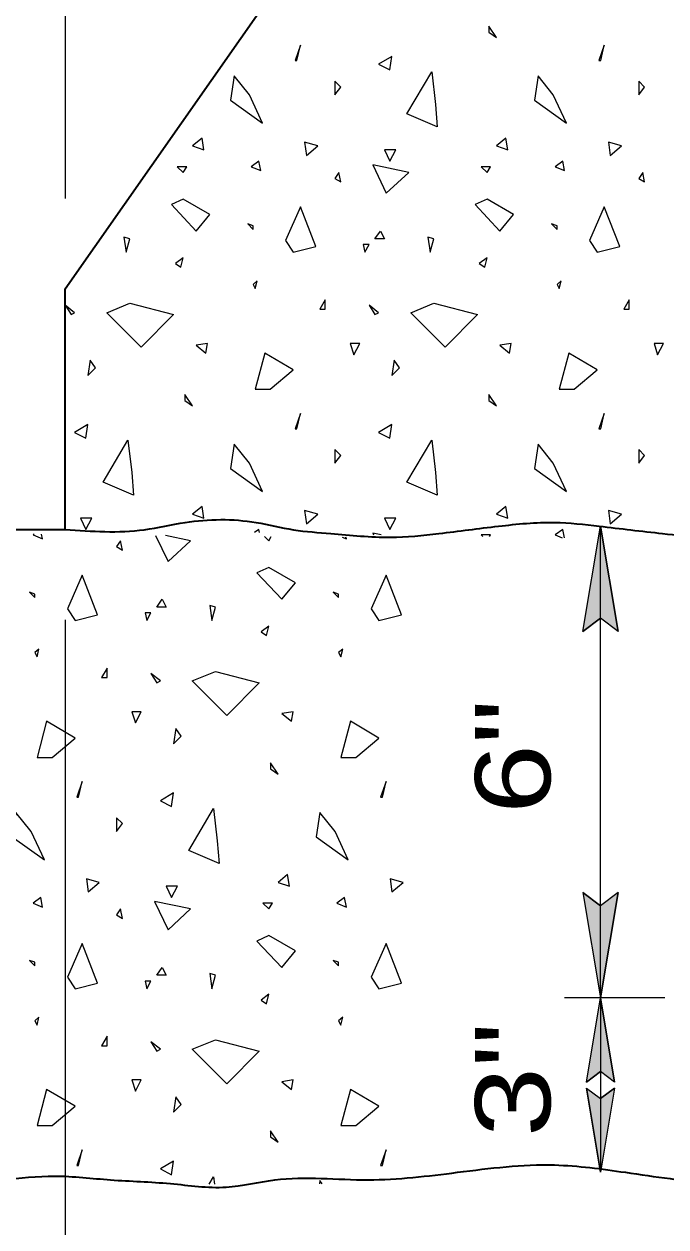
# Model space of a CAD drawing. Extents: x -9.07 to -2.08, y 8.04 to 17.77.
# Drawn here: x -6.844 to -6.332, y 13.739 to 14.699 of the extents above; entities that cross this region are included whole.
import ezdxf
from ezdxf.enums import TextEntityAlignment as Align

# ---------------------------------------------------------------- set-up
doc = ezdxf.new("R2010")
doc.units = 0
doc.header["$LTSCALE"] = 0.024
for name, color, linetype, lineweight in [('1', 7, 'Continuous', 35), ('10', 7, 'Continuous', 13), ('12', 7, 'Continuous', 53), ('6', 7, 'Continuous', 13)]:
    doc.layers.add(name, color=color, linetype=linetype, lineweight=lineweight)

msp = doc.modelspace()

# ---------------------------------------------------------------- hatches: boundary and pattern name
at = {"layer": '10'}
for points in [[(-6.38383, 14.29833), (-6.36983, 14.21433), (-6.38383, 14.22483), (-6.39783, 14.21433)], [(-6.38383, 13.922), (-6.36983, 14.00617), (-6.38383, 13.9955), (-6.39783, 14.00617)], [(-6.38383, 13.922), (-6.37267, 13.85483), (-6.38383, 13.86333), (-6.395, 13.85483)], [(-6.38383, 13.84167), (-6.37267, 13.85), (-6.38383, 13.78283), (-6.395, 13.85)]]:
    msp.add_hatch(color=256, dxfattribs=at).paths.add_polyline_path(points)

# ---------------------------------------------------------------- linework, layer by layer
at = {"layer": '1'}
msp.add_lwpolyline([(-7.227, 13.773), (-7.227, 14.29567), (-6.81067, 14.29567), (-6.81067, 14.48783), (-6.4615, 14.98667)], dxfattribs=at)
at = {"layer": '10'}
for p, q in [((-6.81067, 17.69383), (-6.81067, 14.55983)), ((-6.39783, 14.21433), (-6.38383, 14.29833)), ((-6.38383, 13.922), (-6.38383, 14.29833)), ((-6.36983, 14.21433), (-6.38383, 14.29833)), ((-6.81067, 14.22367), (-6.81067, 13.45733)), ((-6.39783, 14.21433), (-6.38383, 14.22483)), ((-6.36983, 14.21433), (-6.38383, 14.22483)), ((-6.39783, 14.00617), (-6.38383, 13.922)), ((-6.39783, 14.00617), (-6.38383, 13.9955)), ((-6.36983, 14.00617), (-6.38383, 13.922)), ((-6.36983, 14.00617), (-6.38383, 13.9955)), ((-6.33267, 13.922), (-6.41267, 13.922)), ((-6.395, 13.85483), (-6.38383, 13.922)), ((-6.38383, 13.922), (-6.38383, 13.78283)), ((-6.37267, 13.85483), (-6.38383, 13.922)), ((-6.395, 13.85483), (-6.38383, 13.86333)), ((-6.37267, 13.85483), (-6.38383, 13.86333)), ((-6.395, 13.85), (-6.38383, 13.78283)), ((-6.395, 13.85), (-6.38383, 13.84167)), ((-6.37267, 13.85), (-6.38383, 13.78283)), ((-6.37267, 13.85), (-6.38383, 13.84167))]:
    msp.add_line(p, q, dxfattribs=at)
for points in [[(-6.38383, 14.29833), (-6.36983, 14.21433), (-6.38383, 14.22483), (-6.39783, 14.21433)], [(-6.38383, 13.922), (-6.36983, 14.00617), (-6.38383, 13.9955), (-6.39783, 14.00617)], [(-6.38383, 13.922), (-6.37267, 13.85483), (-6.38383, 13.86333), (-6.395, 13.85483)], [(-6.38383, 13.84167), (-6.37267, 13.85), (-6.38383, 13.78283), (-6.395, 13.85)]]:
    msp.add_lwpolyline(points, close=True, dxfattribs=at)
at = {"layer": '10', "lineweight": 35}
for points in [[(-6.81067, 14.29567), (-6.74767, 14.2955), (-6.715, 14.30133), (-6.6585, 14.30133), (-6.62867, 14.2955), (-6.599, 14.2925), (-6.55133, 14.2895), (-6.51267, 14.2925), (-6.46517, 14.29833), (-6.4205, 14.30133), (-6.38483, 14.29833), (-6.33433, 14.2925), (-6.27183, 14.2865), (-6.21533, 14.2895), (-6.141, 14.31917), (-6.10233, 14.31317), (-6.03383, 14.30733), (-5.9715, 14.32217), (-5.9, 14.337), (-5.86133, 14.334), (-5.81683, 14.325), (-5.77217, 14.334), (-5.7245, 14.34283), (-5.674, 14.34583), (-5.6115, 14.33983), (-5.59367, 14.33983), (-5.57283, 14.34583), (-5.54017, 14.35767), (-5.4985, 14.3725), (-5.43017, 14.3725), (-5.39733, 14.38133), (-5.3765, 14.40217), (-5.34983, 14.417), (-5.32, 14.417), (-5.28433, 14.414), (-5.26067, 14.414), (-5.22783, 14.42283), (-5.216, 14.42883), (-5.19733, 14.4195)], [(-7.227, 13.773), (-7.173, 13.768), (-7.10767, 13.77383), (-7.057, 13.77683), (-7.0095, 13.771), (-6.97083, 13.771), (-6.947, 13.771), (-6.8875, 13.77383), (-6.86067, 13.77683), (-6.819, 13.77983), (-6.7745, 13.77683), (-6.72683, 13.77383), (-6.68233, 13.771), (-6.64367, 13.77683), (-6.56917, 13.77683), (-6.49783, 13.78283), (-6.4205, 13.78867), (-6.364, 13.78283), (-6.29267, 13.77383), (-6.23017, 13.771), (-6.144, 13.768), (-6.04883, 13.771), (-5.9685, 13.77983), (-5.897, 13.78867), (-5.79, 13.78283), (-5.70967, 13.771), (-5.6085, 13.765), (-5.53717, 13.765), (-5.4895, 13.768), (-5.436, 13.77983), (-5.3855, 13.78867), (-5.323, 13.78867), (-5.2725, 13.77983), (-5.23083, 13.77383), (-5.16533, 13.765), (-5.094, 13.762), (-4.99883, 13.77683), (-4.94533, 13.78283), (-4.88883, 13.78283), (-4.84417, 13.77683), (-4.82333, 13.77383), (-4.78083, 13.75633), (-4.8115, 13.771)]]:
    msp.add_spline(points, degree=3, dxfattribs=at)
at = {"layer": '6'}
for points in [[(-6.473, 14.69717), (-6.473, 14.6925), (-6.46683, 14.68817)], [(-6.62733, 14.66983), (-6.626, 14.66983), (-6.623, 14.682)], [(-6.38517, 14.66983), (-6.38367, 14.66983), (-6.38083, 14.682)], [(-6.56083, 14.667), (-6.55183, 14.66233), (-6.55033, 14.673)], [(-6.676, 14.65767), (-6.67883, 14.63817), (-6.65333, 14.61983), (-6.66383, 14.6425)], [(-6.5155, 14.63483), (-6.514, 14.61683), (-6.53817, 14.62733), (-6.51833, 14.66083)], [(-6.43367, 14.65767), (-6.4365, 14.63817), (-6.411, 14.61983), (-6.4215, 14.6425)], [(-6.59567, 14.65333), (-6.59567, 14.6425), (-6.591, 14.64867)], [(-6.35333, 14.65333), (-6.35333, 14.6425), (-6.34867, 14.64867)], [(-6.7015, 14.60783), (-6.70917, 14.60183), (-6.70017, 14.5985)], [(-6.45933, 14.60783), (-6.46683, 14.60183), (-6.45783, 14.5985)], [(-6.61983, 14.60467), (-6.61833, 14.59417), (-6.60933, 14.60183)], [(-6.55617, 14.5985), (-6.55183, 14.5895), (-6.54717, 14.5985)], [(-6.3775, 14.60467), (-6.37617, 14.59417), (-6.367, 14.60183)], [(-6.66233, 14.58517), (-6.65483, 14.582), (-6.65617, 14.5895)], [(-6.42, 14.58517), (-6.4125, 14.582), (-6.41383, 14.5895)], [(-6.72133, 14.58517), (-6.71667, 14.5805), (-6.71383, 14.58517)], [(-6.59567, 14.57583), (-6.591, 14.573), (-6.5925, 14.5805)], [(-6.5655, 14.58667), (-6.55467, 14.564), (-6.53667, 14.5805)], [(-6.479, 14.58517), (-6.47433, 14.5805), (-6.4715, 14.58517)], [(-6.35333, 14.57583), (-6.34867, 14.573), (-6.35017, 14.5805)], [(-6.726, 14.555), (-6.70633, 14.53367), (-6.6955, 14.547), (-6.71667, 14.55933)], [(-6.48367, 14.555), (-6.464, 14.53367), (-6.45317, 14.547), (-6.47433, 14.55933)], [(-6.62883, 14.51683), (-6.61083, 14.5215), (-6.623, 14.55317), (-6.635, 14.52617)], [(-6.3865, 14.51683), (-6.3685, 14.5215), (-6.38083, 14.55317), (-6.39267, 14.52617)], [(-6.66083, 14.538), (-6.66517, 14.5395), (-6.66083, 14.53517)], [(-6.55933, 14.53367), (-6.55617, 14.52767), (-6.56367, 14.52767)], [(-6.4185, 14.538), (-6.42283, 14.5395), (-6.4185, 14.53517)], [(-6.76383, 14.529), (-6.762, 14.51683), (-6.75917, 14.52767)], [(-6.573, 14.523), (-6.57167, 14.51683), (-6.56833, 14.523)], [(-6.5215, 14.529), (-6.51967, 14.51683), (-6.51683, 14.52767)], [(-6.72283, 14.50783), (-6.7185, 14.505), (-6.71667, 14.5125)], [(-6.4805, 14.50783), (-6.47617, 14.505), (-6.47433, 14.5125)], [(-6.65767, 14.49417), (-6.66083, 14.49117), (-6.65917, 14.488)], [(-6.41533, 14.49417), (-6.4185, 14.49117), (-6.41683, 14.488)], [(-6.81067, 14.47467), (-6.806, 14.46717), (-6.80317, 14.4685)], [(-6.75917, 14.47617), (-6.72433, 14.46717), (-6.75017, 14.44117), (-6.7775, 14.4685)], [(-6.60333, 14.479), (-6.60767, 14.4715), (-6.60333, 14.4715)], [(-6.56367, 14.46717), (-6.56083, 14.4685), (-6.56833, 14.47467)], [(-6.51683, 14.47617), (-6.482, 14.46717), (-6.50783, 14.44117), (-6.53517, 14.4685)], [(-6.361, 14.479), (-6.36533, 14.4715), (-6.361, 14.4715)], [(-6.70633, 14.44267), (-6.69867, 14.4365), (-6.69733, 14.444)], [(-6.5835, 14.444), (-6.58067, 14.435), (-6.57583, 14.444)], [(-6.464, 14.44267), (-6.45633, 14.4365), (-6.455, 14.444)], [(-6.34117, 14.444), (-6.33833, 14.435), (-6.33367, 14.444)], [(-6.64717, 14.40767), (-6.62883, 14.42317), (-6.6515, 14.4365), (-6.65917, 14.40767)], [(-6.40483, 14.40767), (-6.3865, 14.42317), (-6.40917, 14.4365), (-6.41683, 14.40767)], [(-6.79083, 14.43083), (-6.79267, 14.4185), (-6.7865, 14.42467)], [(-6.5485, 14.43083), (-6.55033, 14.4185), (-6.54417, 14.42467)], [(-6.71533, 14.40333), (-6.71533, 14.39867), (-6.70917, 14.39433)], [(-6.473, 14.40333), (-6.473, 14.39867), (-6.46683, 14.39433)], [(-6.62733, 14.376), (-6.626, 14.376), (-6.623, 14.38833)], [(-6.38517, 14.376), (-6.38367, 14.376), (-6.38083, 14.38833)], [(-6.80317, 14.37317), (-6.79417, 14.3685), (-6.79267, 14.37933)], [(-6.56083, 14.37317), (-6.55183, 14.3685), (-6.55033, 14.37933)], [(-6.75767, 14.34117), (-6.75633, 14.32317), (-6.7805, 14.3335), (-6.76067, 14.367)], [(-6.5155, 14.34117), (-6.514, 14.32317), (-6.53817, 14.3335), (-6.51833, 14.367)], [(-6.676, 14.36383), (-6.67883, 14.34433), (-6.65333, 14.326), (-6.66383, 14.34867)], [(-6.59567, 14.3595), (-6.59567, 14.34867), (-6.591, 14.35483)], [(-6.43367, 14.36383), (-6.4365, 14.34433), (-6.411, 14.326), (-6.4215, 14.34867)], [(-6.35333, 14.3595), (-6.35333, 14.34867), (-6.34867, 14.35483)], [(-6.7015, 14.31417), (-6.70917, 14.308), (-6.70017, 14.30467)], [(-6.61983, 14.31083), (-6.61833, 14.30033), (-6.60933, 14.308)], [(-6.45933, 14.31417), (-6.46683, 14.308), (-6.45783, 14.30467)], [(-6.3775, 14.31083), (-6.37617, 14.30033), (-6.367, 14.308)], [(-6.7985, 14.30467), (-6.79417, 14.29567), (-6.7895, 14.30467)], [(-6.55617, 14.30467), (-6.55183, 14.29567), (-6.54717, 14.30467)], [(-6.76967, 14.282), (-6.765, 14.27917), (-6.7665, 14.28667)], [(-6.65783, 14.26117), (-6.638, 14.24), (-6.62717, 14.25317), (-6.64833, 14.2655)], [(-6.80283, 14.223), (-6.78483, 14.22767), (-6.79717, 14.25933), (-6.809, 14.23233)], [(-6.5605, 14.223), (-6.5425, 14.22767), (-6.55483, 14.25933), (-6.56667, 14.23233)], [(-6.835, 14.24417), (-6.83917, 14.24567), (-6.835, 14.24133)], [(-6.59267, 14.24417), (-6.597, 14.24567), (-6.59267, 14.24133)], [(-6.73333, 14.24), (-6.73017, 14.23383), (-6.73767, 14.23383)], [(-6.6955, 14.23517), (-6.69383, 14.223), (-6.69083, 14.23383)], [(-6.747, 14.22917), (-6.74567, 14.223), (-6.74233, 14.22917)], [(-6.6545, 14.214), (-6.65017, 14.21117), (-6.64833, 14.21867)], [(-6.83167, 14.20033), (-6.835, 14.1975), (-6.83317, 14.19417)], [(-6.58933, 14.20033), (-6.59267, 14.1975), (-6.59083, 14.19417)], [(-6.77733, 14.18517), (-6.78167, 14.17767), (-6.77733, 14.17767)], [(-6.73767, 14.17333), (-6.73483, 14.17483), (-6.74233, 14.18083)], [(-6.69083, 14.18233), (-6.656, 14.17333), (-6.68183, 14.14733), (-6.70933, 14.17483)], [(-6.7575, 14.15033), (-6.75467, 14.14133), (-6.75, 14.15033)], [(-6.638, 14.14883), (-6.63033, 14.14267), (-6.629, 14.15033)], [(-6.82117, 14.11383), (-6.80283, 14.12933), (-6.8255, 14.14267), (-6.83317, 14.11383)], [(-6.7225, 14.137), (-6.72433, 14.12467), (-6.71833, 14.13083)], [(-6.57883, 14.11383), (-6.5605, 14.12933), (-6.58317, 14.14267), (-6.59083, 14.11383)], [(-6.647, 14.1095), (-6.647, 14.10483), (-6.64083, 14.1005)], [(-6.8015, 14.08217), (-6.8, 14.08217), (-6.79717, 14.0945)], [(-6.55917, 14.08217), (-6.55767, 14.08217), (-6.55483, 14.0945)], [(-6.73483, 14.07933), (-6.72583, 14.07467), (-6.72433, 14.0855)], [(-6.85, 14.07), (-6.853, 14.0505), (-6.82733, 14.03217), (-6.83783, 14.05483)], [(-6.6895, 14.04733), (-6.688, 14.02933), (-6.71217, 14.03967), (-6.69233, 14.07317)], [(-6.60767, 14.07), (-6.61067, 14.0505), (-6.585, 14.03217), (-6.5955, 14.05483)], [(-6.76967, 14.06567), (-6.76967, 14.05483), (-6.765, 14.061)], [(-6.79383, 14.017), (-6.7925, 14.00667), (-6.7835, 14.01417)], [(-6.63333, 14.02033), (-6.64083, 14.01417), (-6.63183, 14.011)], [(-6.5515, 14.017), (-6.55017, 14.00667), (-6.54117, 14.01417)], [(-6.73017, 14.011), (-6.72583, 14.002), (-6.72117, 14.011)], [(-6.83633, 13.99767), (-6.82883, 13.99433), (-6.83017, 14.002)], [(-6.76967, 13.98817), (-6.765, 13.98533), (-6.7665, 13.993)], [(-6.7395, 13.999), (-6.72867, 13.97633), (-6.71067, 13.993)], [(-6.65317, 13.99767), (-6.64833, 13.993), (-6.6455, 13.99767)], [(-6.594, 13.99767), (-6.5865, 13.99433), (-6.588, 14.002)], [(-6.80283, 13.92917), (-6.78483, 13.93383), (-6.79717, 13.9655), (-6.809, 13.9385)], [(-6.65783, 13.96733), (-6.638, 13.94617), (-6.62717, 13.9595), (-6.64833, 13.97167)], [(-6.5605, 13.92917), (-6.5425, 13.93383), (-6.55483, 13.9655), (-6.56667, 13.9385)], [(-6.835, 13.9505), (-6.83917, 13.95183), (-6.835, 13.9475)], [(-6.73333, 13.94617), (-6.73017, 13.94), (-6.73767, 13.94)], [(-6.59267, 13.9505), (-6.597, 13.95183), (-6.59267, 13.9475)], [(-6.747, 13.93533), (-6.74567, 13.92917), (-6.74233, 13.93533)], [(-6.6955, 13.9415), (-6.69383, 13.92917), (-6.69083, 13.94)], [(-6.6545, 13.92017), (-6.65017, 13.91733), (-6.64833, 13.92483)], [(-6.83167, 13.9065), (-6.835, 13.90367), (-6.83317, 13.90033)], [(-6.58933, 13.9065), (-6.59267, 13.90367), (-6.59083, 13.90033)], [(-6.77733, 13.89133), (-6.78167, 13.88383), (-6.77733, 13.88383)], [(-6.73767, 13.8795), (-6.73483, 13.881), (-6.74233, 13.887)], [(-6.69083, 13.8885), (-6.656, 13.8795), (-6.68183, 13.8535), (-6.70933, 13.881)], [(-6.82117, 13.82017), (-6.80283, 13.8355), (-6.8255, 13.84883), (-6.83317, 13.82017)], [(-6.7575, 13.8565), (-6.75467, 13.8475), (-6.75, 13.8565)], [(-6.638, 13.855), (-6.63033, 13.84883), (-6.629, 13.8565)], [(-6.57883, 13.82017), (-6.5605, 13.8355), (-6.58317, 13.84883), (-6.59083, 13.82017)], [(-6.7225, 13.84317), (-6.72433, 13.83083), (-6.71833, 13.837)], [(-6.647, 13.81583), (-6.647, 13.81117), (-6.64083, 13.80683)], [(-6.8015, 13.78833), (-6.8, 13.78833), (-6.79717, 13.80067)], [(-6.55917, 13.78833), (-6.55767, 13.78833), (-6.55483, 13.80067)], [(-6.73483, 13.7855), (-6.72583, 13.78083), (-6.72433, 13.79167)]]:
    msp.add_lwpolyline(points, close=True, dxfattribs=at)
for points in [[(-6.8355, 14.292), (-6.83633, 14.29133), (-6.82883, 14.28817), (-6.8295, 14.292)], [(-6.73867, 14.291), (-6.72867, 14.27017), (-6.71067, 14.28667), (-6.73067, 14.291)], [(-6.65567, 14.29317), (-6.65617, 14.29567), (-6.65983, 14.29317)], [(-6.65183, 14.29017), (-6.64833, 14.28667), (-6.64633, 14.29017)], [(-6.55883, 14.2915), (-6.5655, 14.29283), (-6.56483, 14.2915)], [(-6.47233, 14.29), (-6.4715, 14.29133), (-6.479, 14.29133), (-6.47767, 14.29017)], [(-6.41267, 14.289), (-6.41383, 14.29567), (-6.42, 14.29133), (-6.41433, 14.289)], [(-6.58983, 14.28967), (-6.5865, 14.28817), (-6.58683, 14.28967)], [(-6.69583, 13.7735), (-6.69233, 13.77933), (-6.69167, 13.7735)], [(-6.60567, 13.77367), (-6.60767, 13.77617), (-6.608, 13.77367)]]:
    msp.add_lwpolyline(points, dxfattribs=at)

# ---------------------------------------------------------------- texts
at = {"layer": '12', "width": 1.25}
for s, p in [('6"', (-6.42383, 14.11442)), ('3"', (-6.42383, 13.85667))]:
    msp.add_text(s, height=0.06001, rotation=90, dxfattribs=at).set_placement(p, align=Align.CENTER)

doc.saveas('drawing.dxf')
